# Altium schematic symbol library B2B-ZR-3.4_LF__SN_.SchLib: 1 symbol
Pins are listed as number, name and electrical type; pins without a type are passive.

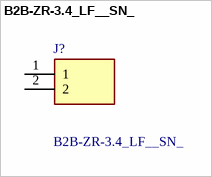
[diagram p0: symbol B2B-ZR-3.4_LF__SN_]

## B2B-ZR-3.4_LF__SN_
designator J?
CONN HEADER VERT 2POS 1.5MM; Manufacturer_Name: JST (JAPAN SOLDERLESS TERMINALS); Manufacturer_Part_Number: B2B-ZR-3.4(LF)(SN); Geometry.Height: 4.5mm
footprint SHDR2W50P0X150_1X2_450X350X450P
pins: 1, 2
